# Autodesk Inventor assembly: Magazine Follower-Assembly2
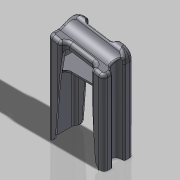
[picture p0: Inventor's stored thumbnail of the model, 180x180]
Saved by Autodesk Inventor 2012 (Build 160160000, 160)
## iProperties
Category: Gun
Company: MH Vaaben Teknik
Created: 2011-12
Part Number: Magazine Follower-Assembly2
Document SubType Name: Assembly
Designer: Michael Høgh
Project: Sten MK II
Material: Steel, Mild
Engineer: Michael Høgh
Mass: 29.1128 g
Surface Area: 87.9415 cm^2
Volume: 3.69921 cm^3
Density: 7.87 g/cm^3
Author: Michael Høgh
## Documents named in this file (3)
- C:\Users\Michael Høgh\Dropbox\Documents\TEC-Ballerup\I - Inventor\2011\Ideer\Sten MK II\Assemblies\Magazine Follower-Assembly2.iam
- C:\Users\Michael Høgh\Dropbox\Documents\TEC-Ballerup\I - Inventor\2011\Ideer\Sten MK II\Parts\Magazine Follower Spring Stop.ipt
- C:\Users\Michael Høgh\Dropbox\Documents\TEC-Ballerup\I - Inventor\2011\Ideer\Sten MK II\Parts\Magazine Follower.ipt
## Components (2 placed, 2 different names)
1. Magazine Follower:1 — Mate:1, Mate:2, Mate:3, Mate:4
2. Magazine Follower Spring Stop:1 — Mate:1, Mate:2, Mate:3, Mate:4
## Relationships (4: Mate 4)
- Mate:1: Magazine Follower:1 ↔ Magazine Follower Spring Stop:1
- Mate:2: Magazine Follower:1 ↔ Magazine Follower Spring Stop:1
- Mate:3: Magazine Follower:1 ↔ Magazine Follower Spring Stop:1
- Mate:4: Magazine Follower:1 ↔ Magazine Follower Spring Stop:1
